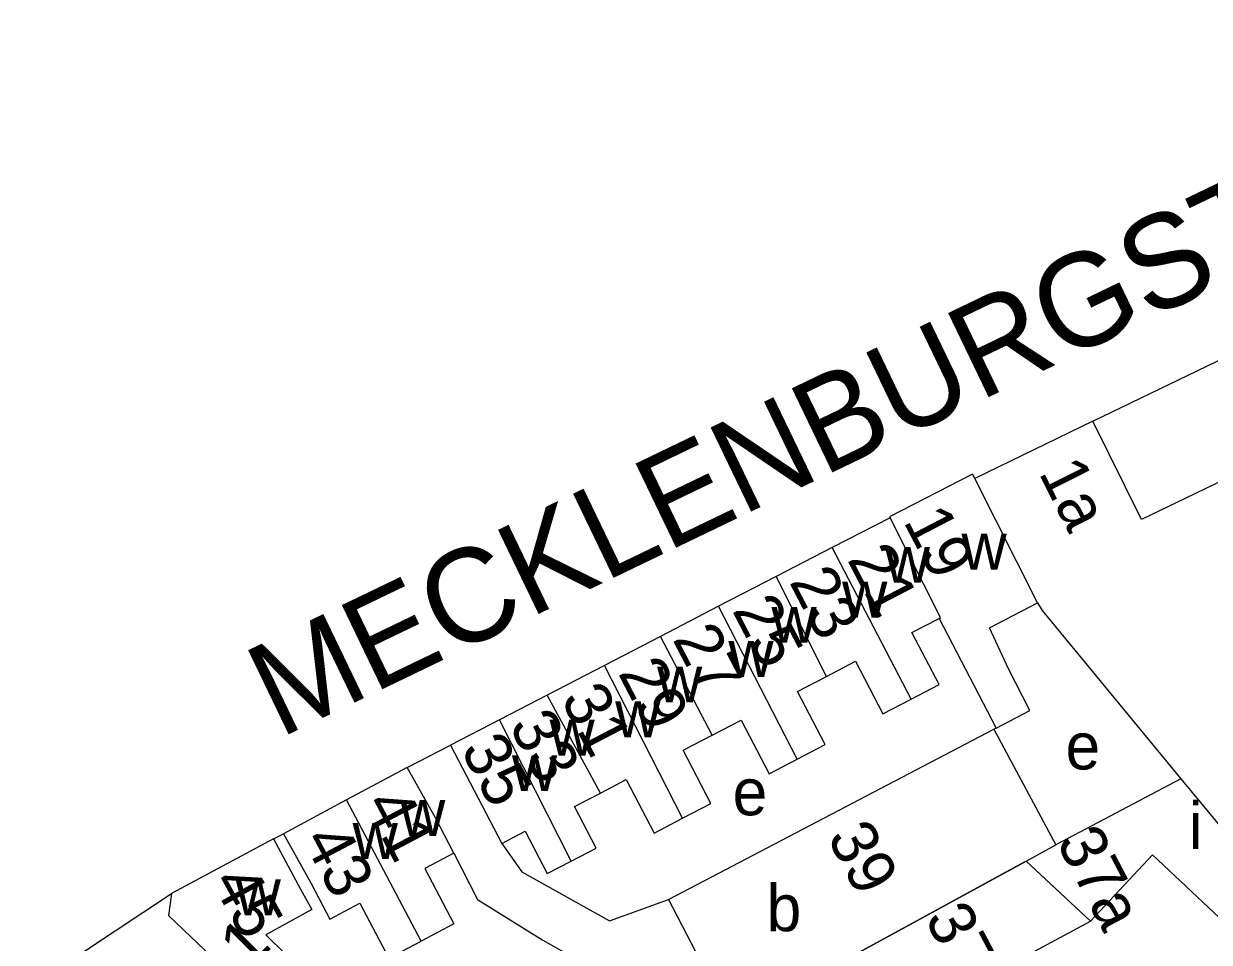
# Model space of a CAD drawing. Extents: x 159700 to 161346, y 381730 to 382922.
# Drawn here: x 160730.2 to 160831.8, y 382840.5 to 382919.2 of the extents above; entities that cross this region are included whole.
import ezdxf

# ---------------------------------------------------------------- set-up
doc = ezdxf.new("R2010")
doc.units = 0
for name, color, linetype in [('BLT_Basislijn', 7, 'Continuous'), ('BLT_Bebouwing', 7, 'Continuous'), ('BLT_Centroide', 7, 'Continuous'), ('BLT_Huisnummer', 7, 'Continuous'), ('BLT_Huisnummer_ tussenligend', 7, 'Continuous'), ('BLT_Huisnummer_reeks', 7, 'Continuous'), ('BLT_Huisnummer_zonder_bebouwing', 7, 'Continuous'), ('BLT_Onderdoorgang_en_onderverdeling', 7, 'Continuous'), ('BLT_Onderverdeling_panden', 7, 'Continuous'), ('BLT_Plantopo', 7, 'Continuous'), ('BLT_Straatnaam_hoofdweg', 7, 'Continuous'), ('BLT_Vlakafsluiter', 7, 'Continuous')]:
    doc.layers.add(name, color=color, linetype=linetype)

msp = doc.modelspace()

# ---------------------------------------------------------------- linework, layer by layer
at = {"layer": 'BLT_Basislijn'}
for p, q in [((160813.56, 382858.88), (160813.36, 382858.78)), ((160763.09, 382855.51), (160766.8, 382857.43)), ((160751.63, 382849.39), (160752.49, 382849.83))]:
    msp.add_line(p, q, dxfattribs=at)
for points in [[(160771.19, 382848.99), (160772.91, 382846.56), (160780.42, 382842.37), (160785.48, 382844.19)], [(160767.09, 382848.17), (160769.1, 382844.18), (160774.71, 382840.7), (160780.54, 382837.42)]]:
    msp.add_lwpolyline(points, dxfattribs=at)
at = {"layer": 'BLT_Bebouwing'}
for p, q in [((160821.83, 382885.16), (160841.95, 382894.9)), ((160821.83, 382885.16), (160811.72, 382880.26)), ((160804.46, 382876.88), (160799.49, 382874.34)), ((160799.49, 382874.34), (160794.69, 382871.87)), ((160794.69, 382871.87), (160789.76, 382869.32)), ((160789.76, 382869.32), (160784.79, 382866.72)), ((160808.67, 382868.28), (160813.56, 382858.88)), ((160784.79, 382866.72), (160779.99, 382864.24)), ((160779.99, 382864.24), (160775.09, 382861.71)), ((160775.09, 382861.71), (160770.99, 382859.59)), ((160813.56, 382858.88), (160816.45, 382860.38)), ((160770.99, 382859.59), (160766.8, 382857.43)), ((160763.09, 382855.51), (160757.89, 382852.72)), ((160829.39, 382854.52), (160818.68, 382848.87)), ((160829.39, 382854.52), (160836.71, 382845.65)), ((160757.89, 382852.72), (160752.49, 382849.83)), ((160751.63, 382849.39), (160742.88, 382844.7)), ((160785.48, 382844.19), (160790.9, 382833.81))]:
    msp.add_line(p, q, dxfattribs=at)
for points in [[(160811.72, 382880.26), (160811.53, 382880.62), (160804.41, 382876.98), (160804.46, 382876.88)], [(160816.45, 382860.38), (160814.61, 382863.95), (160812.99, 382867.48), (160817.09, 382869.61)], [(160817.09, 382869.61), (160817.49, 382868.95), (160829.39, 382854.52)], [(160806.26, 382861.35), (160808.67, 382862.6), (160806.34, 382867.07), (160808.67, 382868.28)], [(160799.01, 382863.31), (160801.5, 382864.61), (160803.85, 382860.09), (160806.26, 382861.35)], [(160796.51, 382856.22), (160798.9, 382857.46), (160796.53, 382862.02), (160799.01, 382863.31)], [(160789.22, 382858.28), (160791.71, 382859.57), (160794.11, 382854.97), (160796.51, 382856.22)], [(160785.48, 382844.19), (160813.36, 382858.78)], [(160786.68, 382851.15), (160789.11, 382852.42), (160786.73, 382856.98), (160789.22, 382858.28)], [(160813.36, 382858.78), (160818.68, 382848.87)], [(160766.8, 382857.43), (160771.19, 382848.99)], [(160767.09, 382848.17), (160765.51, 382851.18), (160763.09, 382855.51)], [(160779.64, 382853.31), (160781.86, 382854.47), (160784.25, 382849.89), (160786.68, 382851.15)], [(160777.13, 382847.49), (160779.27, 382848.6), (160777.42, 382852.16), (160779.64, 382853.31)], [(160752.49, 382849.83), (160754.86, 382845.56), (160756.44, 382842.52), (160759.01, 382843.87), (160761.5, 382839.16), (160764.29, 382840.63)], [(160771.19, 382848.99), (160773.2, 382850.04), (160775.09, 382846.42), (160777.13, 382847.49)], [(160751.63, 382849.39), (160753.95, 382845.08), (160754.9, 382843.34), (160750.96, 382841.16), (160752.67, 382839.49)], [(160767.09, 382848.17), (160764.58, 382846.86), (160767.09, 382842.11), (160764.29, 382840.63)], [(160816.12, 382847.48), (160821.64, 382842.33), (160826.95, 382848.01), (160833.18, 382842.18)], [(160794.02, 382831.81), (160801.16, 382839.32), (160816.12, 382847.48)], [(160742.88, 382844.7), (160742.63, 382842.83), (160749.48, 382836.29)]]:
    msp.add_lwpolyline(points, dxfattribs=at)
at = {"layer": 'BLT_Onderdoorgang_en_onderverdeling'}
msp.add_lwpolyline([(160841.95, 382894.9), (160846.18, 382886.45), (160826.02, 382876.74), (160821.83, 382885.16)], dxfattribs=at)
at = {"layer": 'BLT_Onderverdeling_panden'}
for p, q in [((160817.09, 382869.61), (160811.72, 382880.26)), ((160806.26, 382861.35), (160799.49, 382874.34)), ((160799.01, 382863.31), (160794.69, 382871.87)), ((160796.51, 382856.22), (160789.76, 382869.32)), ((160789.22, 382858.28), (160784.79, 382866.72)), ((160786.68, 382851.15), (160779.99, 382864.24)), ((160779.64, 382853.31), (160775.09, 382861.71)), ((160777.13, 382847.49), (160770.99, 382859.59)), ((160764.29, 382840.63), (160757.89, 382852.72)), ((160816.12, 382847.48), (160818.68, 382848.87))]:
    msp.add_line(p, q, dxfattribs=at)
msp.add_lwpolyline([(160808.67, 382868.28), (160808.79, 382868.34), (160804.46, 382876.88)], dxfattribs=at)
at = {"layer": 'BLT_Plantopo'}
msp.add_lwpolyline([(160815.95, 382847.39), (160801.16, 382839.32), (160798.93, 382836.95), (160803.55, 382832.6), (160821.64, 382842.33), (160816.46, 382847.17)], dxfattribs=at)
at = {"layer": 'BLT_Vlakafsluiter'}
msp.add_line((160730.22, 382836.35), (160742.88, 382844.7), dxfattribs=at)

# ---------------------------------------------------------------- texts
at = {"layer": 'BLT_Centroide'}
for s, p in [('w', (160810.59, 382872.45)), ('w', (160804.02, 382871.33)), ('w', (160800.36, 382868.34)), ('w', (160794.3, 382866.19)), ('w', (160790.61, 382863.27)), ('w', (160784.5, 382861.08)), ('w', (160780.91, 382858.09)), ('w', (160775.28, 382856.53)), ('e', (160819.5, 382855.34)), ('w', (160772.06, 382853.48)), ('e', (160790.97, 382851.41)), ('w', (160762.48, 382849.64)), ('i', (160830.06, 382848.53)), ('w', (160758.41, 382847.67)), ('w', (160748.38, 382842.84)), ('b', (160793.88, 382841.48))]:
    msp.add_text(s, height=4, dxfattribs=at).set_placement(p)
at = {"layer": 'BLT_Huisnummer'}
for s, rotation, p in [('19', 297.5112, (160805.56, 382876.61)), ('23', 297.505, (160795.78, 382871.42)), ('27', 297.5082, (160785.78, 382866.51)), ('31', 297.5111, (160776.19, 382861.39)), ('35', 297.6289, (160767.61, 382857.07)), ('41', 297.809, (160759.35, 382852.39)), ('39', 297.7811, (160799.02, 382849.54)), ('43', 297.8055, (160754.1, 382849.3)), ('37a', 297.7811, (160818.66, 382849.13))]:
    msp.add_text(s, height=4, rotation=rotation, dxfattribs=at).set_placement(p)
at = {"layer": 'BLT_Huisnummer_ tussenligend'}
for s, rotation, p in [('21', 297.5112, (160800.75, 382873.34)), ('25', 297.505, (160790.89, 382868.98)), ('29', 297.5082, (160781.11, 382863.61)), ('33', 297.5111, (160771.76, 382859.11))]:
    msp.add_text(s, height=4, rotation=rotation, dxfattribs=at).set_placement(p)
at = {"layer": 'BLT_Huisnummer_reeks'}
for s, rotation, p in [('1a', 296.7541, (160817.16, 382880.77)), ('45', 298.8929, (160746.26, 382845.71)), ('1', 45.1704, (160749.49, 382838.03))]:
    msp.add_text(s, height=4, rotation=rotation, dxfattribs=at).set_placement(p)
at = {"layer": 'BLT_Huisnummer_zonder_bebouwing'}
msp.add_text('37b', height=4, rotation=297.7811, dxfattribs=at).set_placement((160807.38, 382842.58))
at = {"layer": 'BLT_Straatnaam_hoofdweg'}
msp.add_text('MECKLENBURGSTRAAT', height=8, rotation=25.714, dxfattribs=at).set_placement((160752.13, 382857.96))

doc.saveas('drawing.dxf')
